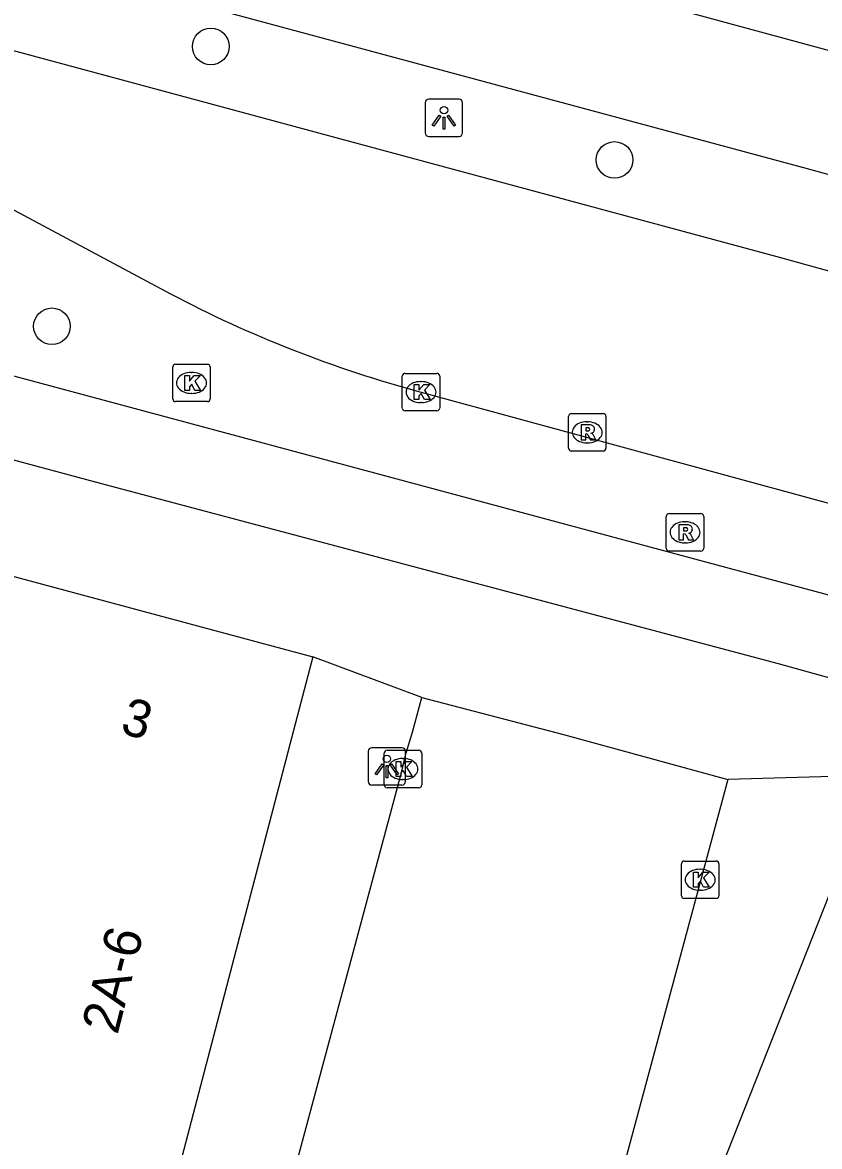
# Model space of a CAD drawing. Extents: x 160676 to 161153, y 383244 to 383713.
# Drawn here: x 160849.7 to 160871.01, y 383552.73 to 383582.77 of the extents above; entities that cross this region are included whole.
import ezdxf

# ---------------------------------------------------------------- set-up
doc = ezdxf.new("R2010")
doc.units = 0
for name, color, linetype in [('IMGEO_Boom', 7, 'Continuous'), ('IMGEO_Fietspad_gesloten', 7, 'Continuous'), ('IMGEO_Kolk', 7, 'Continuous'), ('IMGEO_Lichtpunt', 7, 'Continuous'), ('IMGEO_OVBaan_gesloten', 7, 'Continuous'), ('IMGEO_Pand', 7, 'Continuous'), ('IMGEO_Pand_nummerreeks', 7, 'Continuous'), ('IMGEO_Rijbaan_lokaal_gesloten', 7, 'Continuous'), ('IMGEO_Rijbaan_lokaal_open', 7, 'Continuous'), ('IMGEO_Rioolput', 7, 'Continuous'), ('IMGEO_Voetpad_open', 7, 'Continuous')]:
    doc.layers.add(name, color=color, linetype=linetype)

msp = doc.modelspace()

# ---------------------------------------------------------------- linework, layer by layer
at = {"layer": 'IMGEO_Boom'}
for centre in [(160854.735, 383582.13), (160865.529, 383579.098), (160850.486, 383574.652)]:
    msp.add_circle(centre, 0.489, dxfattribs=at)
at = {"layer": 'IMGEO_Fietspad_gesloten'}
for points in [[(160904.417, 383556.04), (160869.912, 383565.633), (160851.652, 383570.489), (160741.54, 383600.127)], [(160753.356, 383599.164), (160754.374, 383598.874), (160872.54, 383567.128), (160873.601, 383566.834)]]:
    msp.add_lwpolyline(points, dxfattribs=at)
at = {"layer": 'IMGEO_Kolk'}
for p, q in [((160853.718, 383572.712), (160853.718, 383573.564)), ((160853.793, 383573.638), (160854.645, 383573.638)), ((160854.719, 383573.564), (160854.719, 383572.712)), ((160854.206, 383573.418), (160854.231, 383573.418)), ((160859.854, 383572.468), (160859.854, 383573.32)), ((160859.929, 383573.394), (160860.781, 383573.394)), ((160860.342, 383573.174), (160860.367, 383573.174)), ((160860.855, 383573.32), (160860.855, 383572.468)), ((160854.229, 383572.858), (160854.204, 383572.858)), ((160854.645, 383572.638), (160853.793, 383572.638)), ((160860.365, 383572.614), (160860.34, 383572.614)), ((160860.781, 383572.394), (160859.929, 383572.394)), ((160859.372, 383562.393), (160859.372, 383563.245)), ((160859.447, 383563.319), (160860.299, 383563.319)), ((160860.373, 383563.245), (160860.373, 383562.393)), ((160859.86, 383563.099), (160859.885, 383563.099)), ((160860.299, 383562.319), (160859.447, 383562.319)), ((160859.883, 383562.539), (160859.858, 383562.539)), ((160867.319, 383559.434), (160867.319, 383560.286)), ((160867.394, 383560.36), (160868.246, 383560.36)), ((160868.32, 383560.286), (160868.32, 383559.434)), ((160867.807, 383560.14), (160867.832, 383560.14)), ((160868.246, 383559.36), (160867.394, 383559.36)), ((160867.83, 383559.58), (160867.805, 383559.58))]:
    msp.add_line(p, q, dxfattribs=at)
for points in [[(160853.718, 383572.712), (160853.718, 383573.564)], [(160853.793, 383573.638), (160854.645, 383573.638)], [(160854.719, 383573.564), (160854.719, 383572.712)], [(160854.039, 383573.338), (160854.162, 383573.338), (160854.162, 383573.187), (160854.292, 383573.338), (160854.456, 383573.338), (160854.31, 383573.187), (160854.463, 383572.938), (160854.311, 383572.938), (160854.226, 383573.102), (160854.162, 383573.035), (160854.162, 383572.938), (160854.039, 383572.938), (160854.039, 383573.338)], [(160859.854, 383572.468), (160859.854, 383573.32)], [(160859.929, 383573.394), (160860.781, 383573.394)], [(160860.855, 383573.32), (160860.855, 383572.468)], [(160860.175, 383573.094), (160860.298, 383573.094), (160860.298, 383572.943), (160860.428, 383573.094), (160860.592, 383573.094), (160860.446, 383572.943), (160860.599, 383572.694), (160860.447, 383572.694), (160860.362, 383572.858), (160860.298, 383572.791), (160860.298, 383572.694), (160860.175, 383572.694), (160860.175, 383573.094)], [(160854.645, 383572.638), (160853.793, 383572.638)], [(160860.781, 383572.394), (160859.929, 383572.394)], [(160859.372, 383562.393), (160859.372, 383563.245)], [(160859.447, 383563.319), (160860.299, 383563.319)], [(160860.373, 383563.245), (160860.373, 383562.393)], [(160859.693, 383563.019), (160859.816, 383563.019), (160859.816, 383562.868), (160859.946, 383563.019), (160860.11, 383563.019), (160859.964, 383562.868), (160860.117, 383562.619), (160859.965, 383562.619), (160859.88, 383562.783), (160859.816, 383562.716), (160859.816, 383562.619), (160859.693, 383562.619), (160859.693, 383563.019)], [(160860.299, 383562.319), (160859.447, 383562.319)], [(160867.319, 383559.434), (160867.319, 383560.286)], [(160867.394, 383560.36), (160868.246, 383560.36)], [(160868.32, 383560.286), (160868.32, 383559.434)], [(160867.64, 383560.06), (160867.763, 383560.06), (160867.763, 383559.909), (160867.893, 383560.06), (160868.057, 383560.06), (160867.911, 383559.909), (160868.064, 383559.66), (160867.912, 383559.66), (160867.827, 383559.824), (160867.763, 383559.757), (160867.763, 383559.66), (160867.64, 383559.66), (160867.64, 383560.06)], [(160868.246, 383559.36), (160867.394, 383559.36)]]:
    msp.add_lwpolyline(points, dxfattribs=at)
for centre, start, end in [((160853.795, 383573.562), 91.552, 178.448), ((160853.795, 383573.562), 91.552, 178.448), ((160854.643, 383573.562), 1.552, 88.448), ((160854.643, 383573.562), 1.552, 88.448), ((160859.931, 383573.318), 91.552, 178.448), ((160859.931, 383573.318), 91.552, 178.448), ((160860.779, 383573.318), 1.552, 88.448), ((160860.779, 383573.318), 1.552, 88.448), ((160853.795, 383572.714), 181.552, 268.448), ((160853.795, 383572.714), 181.552, 268.448), ((160854.643, 383572.714), 271.552, 358.448), ((160854.643, 383572.714), 271.552, 358.448), ((160859.931, 383572.47), 181.552, 268.448), ((160859.931, 383572.47), 181.552, 268.448), ((160860.779, 383572.47), 271.552, 358.448), ((160860.779, 383572.47), 271.552, 358.448), ((160859.449, 383563.243), 91.552, 178.448), ((160859.449, 383563.243), 91.552, 178.448), ((160860.297, 383563.243), 1.552, 88.448), ((160860.297, 383563.243), 1.552, 88.448), ((160859.449, 383562.395), 181.552, 268.448), ((160859.449, 383562.395), 181.552, 268.448), ((160860.297, 383562.395), 271.552, 358.448), ((160860.297, 383562.395), 271.552, 358.448), ((160867.396, 383560.284), 91.552, 178.448), ((160867.396, 383560.284), 91.552, 178.448), ((160868.244, 383560.284), 1.552, 88.448), ((160868.244, 383560.284), 1.552, 88.448), ((160867.396, 383559.436), 181.552, 268.448), ((160867.396, 383559.436), 181.552, 268.448), ((160868.244, 383559.436), 271.552, 358.448), ((160868.244, 383559.436), 271.552, 358.448)]:
    msp.add_arc(centre, 0.0765, start, end, dxfattribs=at)
for centre, major_axis, ratio, start_param, end_param in [((160854.205, 383573.138), (-0.387, 0.002), 0.722429, 4.712389, 7.853982), ((160854.23, 383573.138), (-0.39, 0.002), 0.717154, 1.570796, 4.712389), ((160860.341, 383572.894), (-0.387, 0.002), 0.722429, 4.712389, 7.853982), ((160860.366, 383572.894), (-0.39, 0.002), 0.717154, 1.570796, 4.712389), ((160859.859, 383562.819), (-0.387, 0.002), 0.722429, 4.712389, 7.853982), ((160859.884, 383562.819), (-0.39, 0.002), 0.717154, 1.570796, 4.712389), ((160867.806, 383559.86), (-0.387, 0.002), 0.722429, 4.712389, 7.853982), ((160867.831, 383559.86), (-0.39, 0.002), 0.717154, 1.570796, 4.712389)]:
    msp.add_ellipse(centre, major_axis=major_axis, ratio=ratio, start_param=start_param, end_param=end_param, dxfattribs=at)
at = {"layer": 'IMGEO_Lichtpunt'}
for p, q in [((160861.372, 383580.724), (160860.564, 383580.724)), ((160861.372, 383580.724), (160860.564, 383580.724)), ((160860.47, 383580.629), (160860.47, 383579.822)), ((160860.47, 383580.629), (160860.47, 383579.822)), ((160861.466, 383579.822), (160861.466, 383580.629)), ((160861.466, 383579.822), (160861.466, 383580.629)), ((160860.564, 383579.728), (160861.372, 383579.728)), ((160860.564, 383579.728), (160861.372, 383579.728)), ((160858.944, 383563.293), (160858.944, 383562.486)), ((160858.944, 383563.293), (160858.944, 383562.486)), ((160859.846, 383563.388), (160859.038, 383563.388)), ((160859.846, 383563.388), (160859.038, 383563.388)), ((160859.94, 383562.486), (160859.94, 383563.293)), ((160859.94, 383562.486), (160859.94, 383563.293)), ((160859.038, 383562.392), (160859.846, 383562.392)), ((160859.038, 383562.392), (160859.846, 383562.392))]:
    msp.add_line(p, q, dxfattribs=at)
for points in [[(160860.844, 383580.293), (160860.883, 383580.265), (160860.695, 383580.003), (160860.657, 383580.03), (160860.844, 383580.293)], [(160860.946, 383580.245), (160860.993, 383580.245), (160860.993, 383579.923), (160860.946, 383579.923), (160860.946, 383580.245)], [(160861.056, 383580.265), (160861.094, 383580.292), (160861.281, 383580.03), (160861.242, 383580.002), (160861.056, 383580.265)], [(160859.318, 383562.957), (160859.357, 383562.929), (160859.169, 383562.667), (160859.131, 383562.694), (160859.318, 383562.957)], [(160859.53, 383562.929), (160859.568, 383562.956), (160859.755, 383562.694), (160859.716, 383562.666), (160859.53, 383562.929)], [(160859.42, 383562.909), (160859.467, 383562.909), (160859.467, 383562.587), (160859.42, 383562.587), (160859.42, 383562.909)]]:
    msp.add_lwpolyline(points, dxfattribs=at)
for centre in [(160860.969, 383580.427), (160859.443, 383563.091)]:
    msp.add_circle(centre, 0.0994, dxfattribs=at)
for centre, start, end in [((160860.564, 383580.629), 90, 180), ((160860.564, 383580.629), 90, 180), ((160861.372, 383580.629), 0, 90), ((160861.372, 383580.629), 0, 90), ((160860.564, 383579.822), 180, 270), ((160860.564, 383579.822), 180, 270), ((160861.372, 383579.822), 270, 0), ((160861.372, 383579.822), 270, 360), ((160859.038, 383563.293), 90, 180), ((160859.038, 383563.293), 90, 180), ((160859.846, 383563.293), 0, 90), ((160859.846, 383563.293), 0, 90), ((160859.038, 383562.486), 180, 270), ((160859.038, 383562.486), 180, 270), ((160859.846, 383562.486), 270, 0), ((160859.846, 383562.486), 270, 360)]:
    msp.add_arc(centre, 0.0946, start, end, dxfattribs=at)
at = {"layer": 'IMGEO_OVBaan_gesloten'}
for points in [[(160977.148, 383558.794), (160975.387, 383558.61), (160968.725, 383558.524), (160962.841, 383558.697), (160956.785, 383559.216), (160950.815, 383560.255), (160942.076, 383562.592), (160890.249, 383576.873), (160774.938, 383608.123), (160770.415, 383609.332), (160766.781, 383610.37), (160761.763, 383612.059), (160756.884, 383613.99)], [(160797.835, 383598.49), (160870.684, 383578.867), (160946.568, 383557.927)]]:
    msp.add_lwpolyline(points, dxfattribs=at)
at = {"layer": 'IMGEO_Pand'}
for points in [[(160849.404, 383567.986), (160857.461, 383565.816)], [(160857.461, 383565.816), (160857.143, 383564.601), (160852.917, 383548.465), (160850.324, 383542.913), (160850.028, 383543.072), (160849.994, 383543.081)]]:
    msp.add_lwpolyline(points, dxfattribs=at)
at = {"layer": 'IMGEO_Rijbaan_lokaal_gesloten'}
for points in [[(160913.282, 383564.496), (160869.874, 383576.512), (160797.171, 383596.125)], [(160844.949, 383579.673), (160848.337, 383578.365), (160853.656, 383575.522)], [(160860.355, 383572.895), (160871.092, 383569.968), (160874.194, 383569.11)]]:
    msp.add_lwpolyline(points, dxfattribs=at)
msp.add_arc((160868.647, 383603.896), 32.091, 242.1503, 255.0247, dxfattribs=at)
at = {"layer": 'IMGEO_Rijbaan_lokaal_open'}
for points in [[(160856.929, 383551.908), (160859.831, 383562.723), (160859.957, 383563.251), (160860.129, 383563.804), (160860.38, 383564.733)], [(160860.38, 383564.733), (160864.165, 383563.744), (160868.559, 383562.537)], [(160868.559, 383562.537), (160865.424, 383550.899), (160862.182, 383538.869)]]:
    msp.add_lwpolyline(points, dxfattribs=at)
at = {"layer": 'IMGEO_Rioolput'}
for p, q in [((160864.299, 383571.392), (160864.299, 383572.244)), ((160864.374, 383572.318), (160865.226, 383572.318)), ((160865.3, 383572.244), (160865.3, 383571.392)), ((160864.787, 383572.098), (160864.812, 383572.098)), ((160864.81, 383571.538), (160864.785, 383571.538)), ((160865.226, 383571.318), (160864.374, 383571.318)), ((160866.914, 383568.719), (160866.914, 383569.571)), ((160866.989, 383569.645), (160867.841, 383569.645)), ((160867.915, 383569.571), (160867.915, 383568.719)), ((160867.402, 383569.425), (160867.427, 383569.425)), ((160867.841, 383568.645), (160866.989, 383568.645)), ((160867.425, 383568.865), (160867.4, 383568.865))]:
    msp.add_line(p, q, dxfattribs=at)
for points in [[(160864.299, 383571.392), (160864.299, 383572.244)], [(160864.374, 383572.318), (160865.226, 383572.318)], [(160865.3, 383572.244), (160865.3, 383571.392)], [(160864.888, 383572.016), (160864.636, 383572.018), (160864.636, 383571.618)], [(160864.814, 383571.937), (160864.76, 383571.937), (160864.76, 383571.856)], [(160864.636, 383571.618), (160864.76, 383571.618), (160864.76, 383571.78), (160864.771, 383571.78)], [(160864.76, 383571.856), (160864.812, 383571.856)], [(160864.818, 383571.751), (160864.889, 383571.618), (160865.029, 383571.618), (160864.964, 383571.744)], [(160865.226, 383571.318), (160864.374, 383571.318)], [(160866.914, 383568.719), (160866.914, 383569.571)], [(160866.989, 383569.645), (160867.841, 383569.645)], [(160867.915, 383569.571), (160867.915, 383568.719)], [(160867.503, 383569.343), (160867.251, 383569.345), (160867.251, 383568.945)], [(160867.429, 383569.264), (160867.375, 383569.264), (160867.375, 383569.183)], [(160867.251, 383568.945), (160867.375, 383568.945), (160867.375, 383569.107), (160867.386, 383569.107)], [(160867.375, 383569.183), (160867.427, 383569.183)], [(160867.433, 383569.078), (160867.504, 383568.945), (160867.644, 383568.945), (160867.579, 383569.071)], [(160867.841, 383568.645), (160866.989, 383568.645)]]:
    msp.add_lwpolyline(points, dxfattribs=at)
for centre, radius, start, end in [((160864.376, 383572.242), 0.0765, 91.552, 178.448), ((160864.376, 383572.242), 0.0765, 91.552, 178.448), ((160865.224, 383572.242), 0.0765, 1.552, 88.448), ((160865.224, 383572.242), 0.0765, 1.552, 88.448), ((160864.82, 383571.841), 0.0964, 77.0061, 93.1865), ((160864.834, 383571.898), 0.0378, 276.6634, 79.6772), ((160864.887, 383571.906), 0.109, 350.3612, 89.416), ((160864.77, 383571.727), 0.0533, 26.0293, 88.6989), ((160864.796, 383572.045), 0.19, 274.7715, 282.9687), ((160864.885, 383571.906), 0.112, 277.5842, 350.9817), ((160864.869, 383571.691), 0.108, 29.5134, 73.7905), ((160864.376, 383571.394), 0.0765, 181.552, 268.448), ((160864.376, 383571.394), 0.0765, 181.552, 268.448), ((160865.224, 383571.394), 0.0765, 271.552, 358.448), ((160865.224, 383571.394), 0.0765, 271.552, 358.448), ((160866.991, 383569.569), 0.0765, 91.552, 178.448), ((160866.991, 383569.569), 0.0765, 91.552, 178.448), ((160867.839, 383569.569), 0.0765, 1.552, 88.448), ((160867.839, 383569.569), 0.0765, 1.552, 88.448), ((160867.435, 383569.168), 0.0964, 77.0061, 93.1865), ((160867.449, 383569.225), 0.0378, 276.6634, 79.6772), ((160867.502, 383569.233), 0.109, 350.3612, 89.416), ((160867.385, 383569.054), 0.0533, 26.0293, 88.6989), ((160867.411, 383569.372), 0.19, 274.7715, 282.9687), ((160867.5, 383569.233), 0.112, 277.5842, 350.9817), ((160867.484, 383569.018), 0.108, 29.5134, 73.7905), ((160866.991, 383568.721), 0.0765, 181.552, 268.448), ((160866.991, 383568.721), 0.0765, 181.552, 268.448), ((160867.839, 383568.721), 0.0765, 271.552, 358.448), ((160867.839, 383568.721), 0.0765, 271.552, 358.448)]:
    msp.add_arc(centre, radius, start, end, dxfattribs=at)
for centre, major_axis, ratio, start_param, end_param in [((160864.786, 383571.818), (-0.387, 0.002), 0.722429, 4.712389, 7.853982), ((160864.811, 383571.818), (-0.39, 0.002), 0.717154, 1.570796, 4.712389), ((160867.401, 383569.145), (-0.387, 0.002), 0.722429, 4.712389, 7.853982), ((160867.426, 383569.145), (-0.39, 0.002), 0.717154, 1.570796, 4.712389)]:
    msp.add_ellipse(centre, major_axis=major_axis, ratio=ratio, start_param=start_param, end_param=end_param, dxfattribs=at)
at = {"layer": 'IMGEO_Voetpad_open'}
for points in [[(160860.38, 383564.733), (160857.461, 383565.816)], [(160871.974, 383562.641), (160868.559, 383562.537)], [(160867.046, 383548.766), (160871.287, 383559.494)]]:
    msp.add_lwpolyline(points, dxfattribs=at)

# ---------------------------------------------------------------- texts
at = {"layer": 'IMGEO_Pand_nummerreeks'}
for s, rotation, p in [('3', 344.6046, (160852.282, 383563.788)), ('2A-6', 75.5101, (160852.237, 383555.697))]:
    msp.add_text(s, height=1, rotation=rotation, dxfattribs=at).set_placement(p)

doc.saveas('drawing.dxf')
